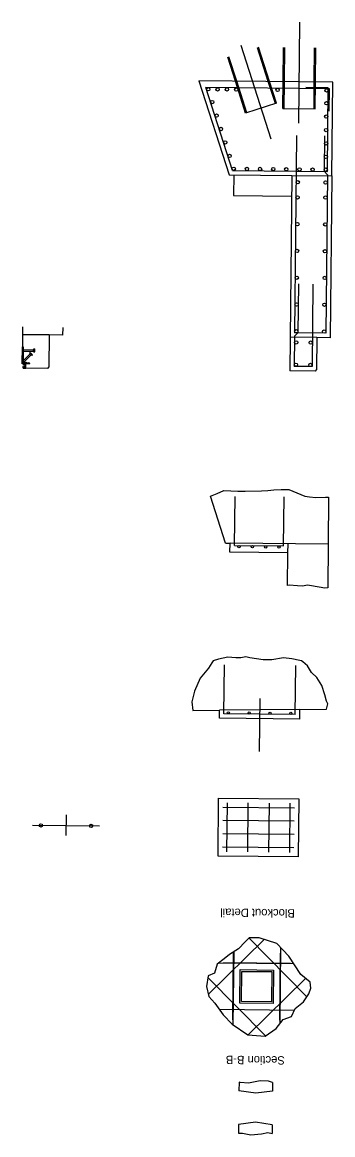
# Model space of a CAD drawing. Extents: x 632022 to 632319, y 373181 to 373252.
# Drawn here: x 632208.55 to 632220.15, y 373195.74 to 373237.29 of the extents above; entities that cross this region are included whole.
import ezdxf

# ---------------------------------------------------------------- set-up
doc = ezdxf.new("R2010")
doc.units = 0
for name, color, linetype in [('B_Boring Annot', 7, 'Continuous'), ('BD-EXIST-COSS', 7, 'Continuous'), ('BD-LEGEND', 7, 'Continuous'), ('BD-PROP-COSS', 7, 'Continuous'), ('BD-PROP-OSB', 7, 'Continuous'), ('BD-REMOVE', 7, 'Continuous'), ('R_Anno_Text', 7, 'Continuous'), ('R_Border_Scale', 7, 'Continuous'), ('R_Proposed Const Limits Cut', 7, 'Continuous'), ('R_Proposed Const Limits Fill', 7, 'Continuous'), ('R_Road Edge of Shoulder', 7, 'Continuous'), ('R_Road Edge of Travel', 7, 'Continuous'), ('R_Shade Removal', 7, 'Continuous'), ('R_Wall', 7, 'Continuous')]:
    doc.layers.add(name, color=color, linetype=linetype)

msp = doc.modelspace()

# ---------------------------------------------------------------- linework, layer by layer
at = {"layer": 'B_Boring Annot'}
msp.add_line((632208.934, 373207.299), (632211.434, 373207.274), dxfattribs=at)
at = {"layer": 'BD-EXIST-COSS'}
msp.add_line((632208.548, 373224.537), (632208.553, 373225.12), dxfattribs=at)
at = {"layer": 'BD-LEGEND'}
for p, q in [((632216.148, 373217.835), (632215.582, 373219.591)), ((632219.999, 373219.547), (632219.981, 373217.797)), ((632216.148, 373217.835), (632216.315, 373217.834)), ((632219.981, 373217.797), (632219.965, 373216.163)), ((632218.466, 373216.251), (632218.478, 373217.479))]:
    msp.add_line(p, q, dxfattribs=at)
at = {"layer": 'BD-PROP-COSS'}
for p, q in [((632216.407, 373231.755), (632215.409, 373234.848)), ((632220.025, 373234.802), (632215.409, 373234.848)), ((632219.984, 373234.844), (632219.151, 373234.852)), ((632219.953, 373231.719), (632219.984, 373234.844)), ((632220.017, 373233.969), (632220.025, 373234.802)), ((632218.799, 373233.057), (632218.726, 373225.686)), ((632219.841, 373233.046), (632219.828, 373231.721)), ((632216.407, 373231.755), (632219.953, 373231.719)), ((632219.828, 373231.721), (632219.952, 373231.594)), ((632219.952, 373231.594), (632219.893, 373225.674)), ((632218.869, 373227.518), (632218.851, 373225.684)), ((632219.411, 373227.512), (632219.38, 373224.429)), ((632218.725, 373225.561), (632218.714, 373224.436)), ((632218.851, 373225.684), (632218.725, 373225.561)), ((632219.893, 373225.674), (632218.726, 373225.686)), ((632219.38, 373224.429), (632218.714, 373224.436)), ((632216.48, 373217.749), (632216.499, 373219.582)), ((632218.314, 373217.731), (632218.332, 373219.564)), ((632216.48, 373217.749), (632218.314, 373217.731)), ((632216.085, 373211.46), (632216.103, 373213.294)), ((632218.751, 373211.434), (632218.769, 373213.267)), ((632218.751, 373211.434), (632216.085, 373211.46)), ((632216.2, 373206.31), (632216.218, 373208.143)), ((632216.978, 373206.302), (632216.996, 373208.135)), ((632217.774, 373208.128), (632217.756, 373206.294)), ((632218.552, 373208.12), (632218.533, 373206.287)), ((632216.05, 373207.978), (632218.717, 373207.951)), ((632218.712, 373207.451), (632216.045, 373207.478)), ((632218.707, 373206.951), (632216.04, 373206.978)), ((632218.702, 373206.452), (632216.035, 373206.478)), ((632215.503, 373200.991), (632217.592, 373203.039)), ((632217.021, 373203.091), (632219.181, 373200.887)), ((632218.201, 373202.737), (632218.173, 373199.883)), ((632216.45, 373202.572), (632216.423, 373199.855)), ((632216.424, 373200.035), (632216.449, 373202.535)), ((632218.174, 373200.018), (632218.199, 373202.518)), ((632215.904, 373202.165), (632218.687, 373202.138)), ((632218.57, 373202.139), (632216.07, 373202.164)), ((632215.489, 373201.618), (632217.633, 373199.431)), ((632216.99, 373199.473), (632219.138, 373201.579)), ((632218.72, 373200.387), (632215.916, 373200.415))]:
    msp.add_line(p, q, dxfattribs=at)
for centre, radius in [((632215.497, 373234.785), 0.0625), ((632215.846, 373234.781), 0.0625), ((632216.195, 373234.778), 0.0625), ((632216.544, 373234.774), 0.0625), ((632218.091, 373234.759), 0.0625), ((632219.92, 373234.741), 0.0625), ((632215.651, 373234.304), 0.0625), ((632219.916, 373234.262), 0.0625), ((632215.813, 373233.802), 0.0625), ((632219.911, 373233.762), 0.0625), ((632215.975, 373233.301), 0.0625), ((632219.906, 373233.262), 0.0625), ((632216.136, 373232.799), 0.0625), ((632219.901, 373232.762), 0.0625), ((632216.298, 373232.297), 0.0625), ((632219.896, 373232.262), 0.0625), ((632216.453, 373231.817), 0.0625), ((632216.944, 373231.812), 0.0625), ((632217.435, 373231.807), 0.0625), ((632217.926, 373231.802), 0.0625), ((632218.417, 373231.797), 0.0625), ((632218.909, 373231.792), 0.0625), ((632219.4, 373231.787), 0.0625), ((632219.891, 373231.782), 0.0625), ((632218.845, 373231.314), 0.0625), ((632219.886, 373231.303), 0.0625), ((632218.839, 373230.747), 0.0625), ((632219.881, 373230.737), 0.0625), ((632218.829, 373229.747), 0.0625), ((632219.871, 373229.737), 0.0625), ((632218.819, 373228.747), 0.0625), ((632219.861, 373228.737), 0.0625), ((632218.809, 373227.747), 0.0625), ((632219.851, 373227.737), 0.0625), ((632218.799, 373226.747), 0.0625), ((632219.841, 373226.737), 0.0625), ((632218.789, 373225.747), 0.0625), ((632219.831, 373225.737), 0.0625), ((632218.785, 373225.331), 0.0625), ((632219.327, 373225.325), 0.0625), ((632218.777, 373224.497), 0.0625), ((632219.319, 373224.492), 0.0625), ((632216.647, 373217.705), 0.0417), ((632217.147, 373217.7), 0.0417), ((632217.647, 373217.695), 0.0417), ((632218.147, 373217.691), 0.0417), ((632216.252, 373211.5), 0.0417), ((632217.029, 373211.493), 0.0417), ((632217.807, 373211.485), 0.0417), ((632218.585, 373211.477), 0.0417)]:
    msp.add_circle(centre, radius, dxfattribs=at)
at = {"layer": 'BD-PROP-OSB'}
for p, q in [((632208.553, 373225.131), (632208.586, 373225.097)), ((632208.553, 373225.086), (632208.586, 373225.053)), ((632208.553, 373225.042), (632208.586, 373225.008)), ((632208.57, 373225.161), (632208.587, 373225.145)), ((632208.549, 373224.643), (632208.654, 373224.536)), ((632208.55, 373224.82), (632208.583, 373224.787)), ((632208.55, 373224.776), (632208.583, 373224.742)), ((632208.551, 373224.909), (632208.584, 373224.875)), ((632208.551, 373224.865), (632208.584, 373224.831)), ((632208.552, 373224.998), (632208.585, 373224.964)), ((632208.552, 373224.953), (632208.585, 373224.92)), ((632208.548, 373224.599), (632208.61, 373224.536)), ((632208.548, 373224.555), (632208.565, 373224.536)), ((632208.633, 373224.602), (632208.698, 373224.535)), ((632208.685, 373224.593), (632208.724, 373224.553)), ((632208.731, 373224.535), (632208.732, 373224.585)), ((632208.738, 373224.535), (632208.739, 373224.584)), ((632208.745, 373224.535), (632208.746, 373224.583)), ((632208.752, 373224.535), (632208.753, 373224.582)), ((632208.759, 373224.535), (632208.759, 373224.581)), ((632208.766, 373224.534), (632208.766, 373224.58)), ((632208.773, 373224.534), (632208.773, 373224.578)), ((632208.78, 373224.534), (632208.78, 373224.577)), ((632208.787, 373224.534), (632208.787, 373224.576)), ((632208.794, 373224.534), (632208.794, 373224.575)), ((632208.801, 373224.534), (632208.801, 373224.573)), ((632208.808, 373224.534), (632208.808, 373224.571)), ((632208.815, 373224.534), (632208.815, 373224.567)), ((632208.822, 373224.534), (632208.822, 373224.56)), ((632208.828, 373224.534), (632208.829, 373224.548))]:
    msp.add_line(p, q, dxfattribs=at)
for points in [[(632208.61, 373224.369), (632208.567, 373224.413)], [(632208.64, 373224.369), (632208.577, 373224.434)], [(632208.599, 373224.503), (632208.584, 373224.518)], [(632208.617, 373224.515), (632208.596, 373224.536)], [(632208.682, 373224.479), (632208.627, 373224.536)], [(632208.671, 373224.369), (632208.627, 373224.414)], [(632208.681, 373224.388), (632208.64, 373224.431)], [(632208.682, 373224.419), (632208.648, 373224.453)], [(632208.682, 373224.449), (632208.652, 373224.48)], [(632208.683, 373224.509), (632208.657, 373224.536)]]:
    msp.add_lwpolyline(points, dxfattribs=at)
at = {"layer": 'R_Anno_Text'}
for centre in [(632209.246, 373207.296), (632211.121, 373207.277)]:
    msp.add_circle(centre, 0.0625, dxfattribs=at)
at = {"layer": 'R_Border_Scale'}
for p, q in [((632218.618, 373231.566), (632220.118, 373231.551)), ((632209.558, 373225.61), (632208.558, 373225.62)), ((632219.558, 373225.511), (632218.558, 373225.521)), ((632219.981, 373217.797), (632216.315, 373217.834)), ((632218.478, 373217.479), (632218.481, 373217.812)), ((632218.92, 373211.629), (632215.919, 373211.599))]:
    msp.add_line(p, q, dxfattribs=at)
at = {"layer": 'R_Proposed Const Limits Cut'}
for p, q in [((632208.548, 373224.537), (632208.554, 373225.162)), ((632208.554, 373225.162), (632208.587, 373225.161)), ((632208.587, 373225.161), (632208.582, 373224.656)), ((632208.586, 373225.062), (632208.975, 373225.058)), ((632208.974, 373224.975), (632208.975, 373225.09)), ((632208.975, 373225.09), (632209.014, 373225.089)), ((632209.013, 373224.975), (632209.014, 373225.089)), ((632208.583, 373224.647), (632208.843, 373224.902)), ((632208.586, 373225.01), (632208.974, 373225.006)), ((632208.615, 373224.606), (632208.879, 373224.865)), ((632208.821, 373224.925), (632208.849, 373224.952)), ((632208.901, 373224.843), (632208.821, 373224.925)), ((632208.929, 373224.87), (632208.849, 373224.952)), ((632208.901, 373224.843), (632208.929, 373224.87)), ((632208.974, 373224.975), (632209.013, 373224.975)), ((632208.724, 373224.535), (632208.548, 373224.537)), ((632208.589, 373224.434), (632208.567, 373224.434)), ((632208.567, 373224.434), (632208.567, 373224.396)), ((632208.567, 373224.396), (632208.583, 373224.37)), ((632208.583, 373224.37), (632208.681, 373224.369)), ((632208.584, 373224.536), (632208.584, 373224.503)), ((632208.584, 373224.503), (632208.606, 373224.503)), ((632208.626, 373224.604), (632208.725, 373224.587)), ((632208.681, 373224.369), (632208.683, 373224.535))]:
    msp.add_line(p, q, dxfattribs=at)
msp.add_arc((632208.635, 373224.656), 0.0529, 179.4304, 259.9304, dxfattribs=at)
msp.add_ellipse((632208.62, 373224.463), major_axis=(0.0134, 0.0564), ratio=0.508295, start_param=2.236026, end_param=7.19143, dxfattribs=at)
at = {"layer": 'R_Proposed Const Limits Fill'}
for p, q in [((632217.424, 373212.034), (632217.404, 373210.054)), ((632210.188, 373207.69), (632210.18, 373206.912))]:
    msp.add_line(p, q, dxfattribs=at)
at = {"layer": 'R_Road Edge of Shoulder'}
for p, q in [((632208.549, 373224.672), (632208.582, 373224.672)), ((632208.55, 373224.735), (632208.583, 373224.734)), ((632208.724, 373224.535), (632208.725, 373224.587)), ((632208.831, 373224.534), (632208.724, 373224.535)), ((632208.725, 373224.587), (632208.797, 373224.574))]:
    msp.add_line(p, q, dxfattribs=at)
msp.add_arc((632208.79, 373224.534), 0.0407, 359.4304, 79.9304, dxfattribs=at)
at = {"layer": 'R_Road Edge of Travel'}
for p, q in [((632217.743, 373235.075), (632217.336, 373236.336)), ((632217.794, 373235.074), (632217.383, 373236.351)), ((632218.294, 373235.069), (632218.307, 373236.342)), ((632218.343, 373235.069), (632218.356, 373236.341)), ((632219.462, 373235.058), (632219.475, 373236.33)), ((632219.511, 373235.057), (632219.524, 373236.33)), ((632216.512, 373235.087), (632216.225, 373235.978)), ((632216.563, 373235.087), (632216.271, 373235.993)), ((632216.897, 373233.891), (632216.512, 373235.087)), ((632216.944, 373233.906), (632216.563, 373235.087)), ((632218.009, 373234.249), (632217.743, 373235.075)), ((632218.055, 373234.264), (632217.794, 373235.074)), ((632218.285, 373234.069), (632218.294, 373235.069)), ((632218.333, 373234.069), (632218.343, 373235.069)), ((632219.452, 373234.058), (632219.462, 373235.058)), ((632219.501, 373234.057), (632219.511, 373235.057)), ((632218.055, 373234.264), (632216.897, 373233.891)), ((632218.285, 373234.069), (632219.501, 373234.057))]:
    msp.add_line(p, q, dxfattribs=at)
at = {"layer": 'R_Shade Removal'}
for p, q in [((632220.153, 373235.051), (632215.153, 373235.101)), ((632215.153, 373235.101), (632216.285, 373231.589)), ((632220.118, 373231.551), (632220.153, 373235.051)), ((632216.285, 373231.589), (632218.618, 373231.566)), ((632216.451, 373231.587), (632216.444, 373230.819)), ((632218.618, 373231.566), (632218.545, 373224.271)), ((632220.118, 373231.551), (632220.058, 373225.506)), ((632216.444, 373230.819), (632218.61, 373230.798)), ((632208.561, 373225.908), (632208.554, 373225.162)), ((632210.061, 373225.893), (632210.058, 373225.605)), ((632209.558, 373225.61), (632209.546, 373224.402)), ((632210.058, 373225.605), (632209.558, 373225.61)), ((632219.558, 373225.511), (632219.546, 373224.302)), ((632220.058, 373225.506), (632219.558, 373225.511)), ((632209.504, 373224.36), (632208.681, 373224.369)), ((632209.504, 373224.36), (632209.546, 373224.402)), ((632219.504, 373224.261), (632218.545, 373224.271)), ((632219.504, 373224.261), (632219.546, 373224.302)), ((632216.311, 373217.5), (632216.315, 373217.834)), ((632218.478, 373217.479), (632216.311, 373217.5)), ((632214.919, 373211.589), (632215.919, 373211.599)), ((632215.916, 373211.295), (632215.919, 373211.599)), ((632218.916, 373211.266), (632218.92, 373211.629)), ((632218.92, 373211.629), (632219.92, 373211.639)), ((632218.916, 373211.266), (632215.916, 373211.295)), ((632216.651, 373197.705), (632216.648, 373197.38)), ((632217.901, 373197.693), (632217.898, 373197.368)), ((632216.636, 373196.13), (632216.632, 373195.805)), ((632217.885, 373196.118), (632217.882, 373195.793))]:
    msp.add_line(p, q, dxfattribs=at)
for points in [[(632215.582, 373219.591), (632215.835, 373219.683), (632216.083, 373219.803), (632216.61, 373219.781), (632216.873, 373219.778), (632217.488, 373219.789), (632217.726, 373219.805), (632217.945, 373219.82), (632218.227, 373219.835), (632218.508, 373219.841), (632218.508, 373219.841), (632219.103, 373219.589), (632219.287, 373219.569), (632219.515, 373219.541), (632219.884, 373219.555), (632219.999, 373219.547)], [(632219.965, 373216.163), (632219.851, 373216.16), (632219.354, 373216.241), (632219.209, 373216.267), (632219.023, 373216.234), (632218.837, 373216.241), (632218.526, 373216.264), (632218.466, 373216.251)], [(632219.92, 373211.639), (632219.963, 373211.831), (632219.923, 373211.931), (632219.923, 373211.931), (632219.856, 373212.168), (632219.738, 373212.516), (632219.551, 373212.824), (632219.362, 373213.002), (632219.204, 373213.249), (632219.039, 373213.407), (632218.985, 373213.437), (632218.919, 373213.453), (632218.624, 373213.521), (632218.308, 373213.55), (632217.876, 373213.484), (632217.549, 373213.477), (632217.053, 373213.557), (632216.908, 373213.584), (632216.722, 373213.55), (632216.536, 373213.557), (632216.225, 373213.58), (632215.883, 373213.508), (632215.686, 373213.44), (632215.635, 373213.36), (632215.503, 373213.171), (632215.203, 373212.787), (632214.982, 373212.312), (632214.883, 373211.911), (632214.919, 373211.589)], [(632217.898, 373197.368), (632217.272, 373197.291), (632216.648, 373197.38)], [(632217.885, 373196.118), (632217.261, 373196.207), (632216.636, 373196.13)]]:
    msp.add_lwpolyline(points, dxfattribs=at)
for points in [[(632218.865, 373206.117), (632215.865, 373206.146), (632215.887, 373208.313), (632218.887, 373208.283)], [(632217.93, 373200.645), (632216.681, 373200.658), (632216.693, 373201.908), (632217.943, 373201.895)], [(632217.869, 373200.708), (632216.744, 373200.719), (632216.755, 373201.844), (632217.88, 373201.833)]]:
    msp.add_lwpolyline(points, close=True, dxfattribs=at)
at = {"layer": 'R_Wall'}
for p, q in [((632218.887, 373233.523), (632218.925, 373237.287)), ((632216.718, 373236.431), (632217.844, 373232.936))]:
    msp.add_line(p, q, dxfattribs=at)
for points in [[(632215.437, 373201.283), (632215.524, 373200.902), (632215.742, 373200.655), (632215.742, 373200.655), (632216.055, 373200.223), (632216.398, 373199.872), (632216.974, 373199.474), (632217.627, 373199.427), (632218.038, 373199.712), (632218.305, 373200.049), (632218.605, 373200.164), (632218.753, 373200.453), (632219.06, 373200.704), (632219.258, 373201.002), (632219.337, 373201.218), (632219.31, 373201.435), (632218.957, 373201.73), (632218.505, 373202.411), (632218.061, 373202.888), (632217.405, 373203.099), (632217.033, 373203.102), (632216.873, 373202.95), (632216.63, 373202.689), (632216.292, 373202.47), (632216.096, 373202.315), (632215.831, 373202.108), (632215.731, 373201.779), (632215.497, 373201.674), (632215.437, 373201.283)], [(632217.901, 373197.693), (632217.755, 373197.746), (632217.437, 373197.755), (632217.004, 373197.666), (632216.69, 373197.696), (632216.651, 373197.705)], [(632216.632, 373195.805), (632216.783, 373195.8), (632217.096, 373195.743), (632217.488, 373195.783), (632217.731, 373195.827), (632217.882, 373195.793)]]:
    msp.add_lwpolyline(points, dxfattribs=at)

# ---------------------------------------------------------------- texts
at = {"layer": 'BD-REMOVE'}
for s, p in [('Blockout Detail', (632218.735, 373204.165)), ('Section B-B', (632218.362, 373198.674))]:
    msp.add_text(s, height=0.3125, rotation=179.4304, dxfattribs=at).set_placement(p)

doc.saveas('drawing.dxf')
